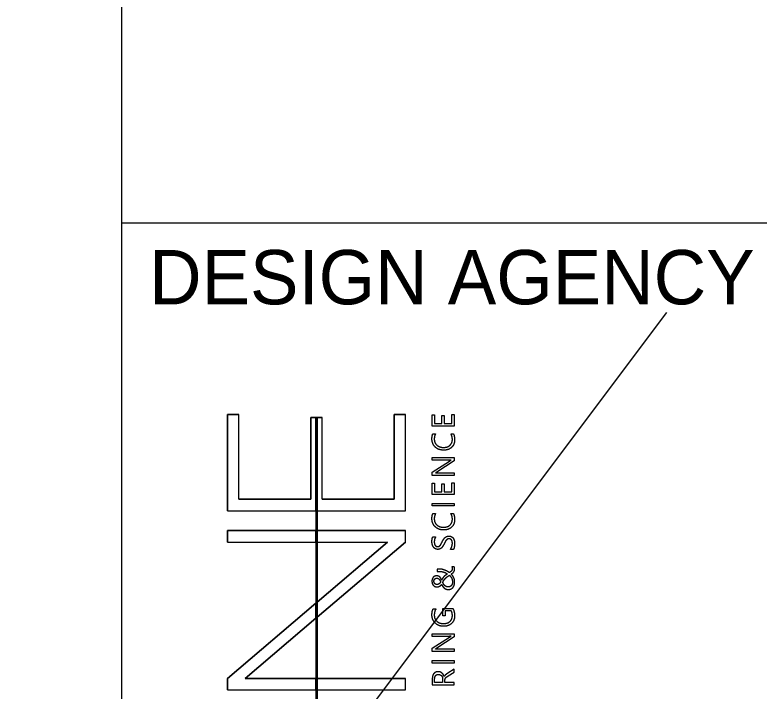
# Model space of a CAD drawing. Extents: x -5.2 to 34, y 0 to 22.
# Drawn here: x 31.803 to 33.173, y 3.638 to 4.883 of the extents above; entities that cross this region are included whole.
import ezdxf

# ---------------------------------------------------------------- set-up
doc = ezdxf.new("R2010")
doc.units = 0
for name, color, linetype in [('CS-ANNO', 7, 'Continuous'), ('CS-ANNO-MATC', 7, 'Continuous'), ('CS-ANNO-VFRM', 7, 'Continuous')]:
    doc.layers.add(name, color=color, linetype=linetype)

msp = doc.modelspace()

# ---------------------------------------------------------------- linework, layer by layer
at = {"layer": 'CS-ANNO'}
for p, q in [((32, 0.5), (32, 21.5)), ((32, 4.5), (33.5, 4.5))]:
    msp.add_line(p, q, dxfattribs=at)
at = {"layer": 'CS-ANNO-MATC'}
for p, q in [((32.1941, 4.1473), (32.2152, 4.1473)), ((32.1941, 3.9702), (32.1941, 4.1473)), ((32.2152, 3.9913), (32.2152, 4.1473)), ((32.3475, 3.9913), (32.3475, 4.1416)), ((32.3475, 4.1416), (32.3567, 4.1416)), ((32.3567, 4.1416), (32.3567, 3.5136)), ((32.3567, 4.1416), (32.3567, 3.9702)), ((32.3567, 4.1416), (32.3593, 4.1416)), ((32.3593, 4.1416), (32.3593, 3.5136)), ((32.3593, 4.1416), (32.3593, 3.9702)), ((32.3593, 4.1416), (32.3685, 4.1416)), ((32.3685, 3.9913), (32.3685, 4.1416)), ((32.5008, 4.1473), (32.5219, 4.1473)), ((32.5008, 3.9913), (32.5008, 4.1473)), ((32.5219, 3.9702), (32.5219, 4.1473)), ((32.5723, 4.1118), (32.5773, 4.1118)), ((32.6054, 4.1118), (32.61, 4.1118)), ((32.6057, 4.0632), (32.6057, 4.0634)), ((32.577, 4.0399), (32.577, 4.0397)), ((32.2152, 3.9913), (32.3475, 3.9913)), ((32.3685, 3.9913), (32.5008, 3.9913)), ((32.1941, 3.9702), (32.3567, 3.9702)), ((32.3593, 3.9702), (32.5219, 3.9702)), ((32.5723, 3.9649), (32.5773, 3.9649)), ((32.6054, 3.9649), (32.61, 3.9649)), ((32.1941, 3.9125), (32.1941, 3.9336)), ((32.1941, 3.9336), (32.3567, 3.9336)), ((32.3567, 3.9336), (32.3567, 3.9125)), ((32.3593, 3.9336), (32.3593, 3.9125)), ((32.3593, 3.9336), (32.5219, 3.9336)), ((32.5219, 3.9125), (32.5219, 3.9336)), ((32.5721, 3.9218), (32.5774, 3.9218)), ((32.1941, 3.9125), (32.3567, 3.9125)), ((32.3593, 3.802), (32.4891, 3.9125)), ((32.5219, 3.9125), (32.3593, 3.7742)), ((32.3593, 3.9125), (32.4891, 3.9125)), ((32.6101, 3.899), (32.6045, 3.899)), ((32.6116, 3.8669), (32.6073, 3.8669)), ((32.5801, 3.8624), (32.5801, 3.858)), ((32.6124, 3.8626), (32.6124, 3.8626)), ((32.5796, 3.846), (32.5796, 3.846)), ((32.6084, 3.839), (32.6084, 3.839)), ((32.1941, 3.6615), (32.3567, 3.7999)), ((32.3567, 3.7999), (32.3567, 3.7721)), ((32.3593, 3.802), (32.3593, 3.7742)), ((32.5728, 3.7895), (32.578, 3.7895)), ((32.3567, 3.7721), (32.2266, 3.6615)), ((32.6057, 3.7391), (32.6057, 3.7392)), ((32.577, 3.7157), (32.577, 3.7156)), ((32.1941, 3.6404), (32.1941, 3.6615)), ((32.2266, 3.6615), (32.3567, 3.6615)), ((32.3567, 3.6615), (32.3567, 3.6404)), ((32.3593, 3.6615), (32.3593, 3.6404)), ((32.3593, 3.6615), (32.5219, 3.6615)), ((32.5219, 3.6404), (32.5219, 3.6615)), ((32.5931, 3.6648), (32.593, 3.6648)), ((32.1941, 3.6404), (32.3567, 3.6404)), ((32.3593, 3.6404), (32.5219, 3.6404))]:
    msp.add_line(p, q, dxfattribs=at)
for points in [[(32.1941, 4.1473), (32.1941, 3.9702), (32.3567, 3.9702), (32.3567, 4.1416), (32.3475, 4.1416), (32.3475, 3.9913), (32.2152, 3.9913), (32.2152, 4.1473)], [(32.3685, 3.9913), (32.3685, 4.1416), (32.3593, 4.1416), (32.3593, 3.9702), (32.5219, 3.9702), (32.5219, 4.1473), (32.5008, 4.1473), (32.5008, 3.9913)], [(32.6117, 4.1473), (32.6117, 4.1258), (32.5713, 4.1258), (32.5713, 4.1464), (32.5756, 4.1464), (32.5756, 4.1306), (32.589, 4.1306), (32.589, 4.1452), (32.5933, 4.1452), (32.5933, 4.1306), (32.6075, 4.1306), (32.6075, 4.1473)], [(32.6117, 4.0216), (32.6117, 4.0002), (32.5713, 4.0002), (32.5713, 4.0207), (32.5756, 4.0207), (32.5756, 4.0049), (32.589, 4.0049), (32.589, 4.0195), (32.5933, 4.0195), (32.5933, 4.0049), (32.6075, 4.0049), (32.6075, 4.0216)], [(32.6117, 3.9837), (32.6117, 3.979), (32.5713, 3.979), (32.5713, 3.9837)], [(32.1941, 3.9336), (32.1941, 3.9125), (32.3567, 3.9125), (32.3567, 3.9336)], [(32.3593, 3.9336), (32.3593, 3.9125), (32.4891, 3.9125), (32.3593, 3.802), (32.3593, 3.7742), (32.5219, 3.9125), (32.5219, 3.9336)], [(32.1941, 3.6615), (32.1941, 3.6404), (32.3567, 3.6404), (32.3567, 3.6615), (32.2266, 3.6615), (32.3567, 3.7721), (32.3567, 3.7999)], [(32.6117, 3.6946), (32.6117, 3.6898), (32.5713, 3.6898), (32.5713, 3.6946)], [(32.3593, 3.6615), (32.3593, 3.6404), (32.5219, 3.6404), (32.5219, 3.6615)]]:
    msp.add_lwpolyline(points, close=True, dxfattribs=at)
for points in [[(32.4683, 3.51), (32.3618, 3.4836), (32.3618, 3.5136), (32.3593, 3.5136), (32.3593, 4.1416), (32.3567, 4.1416), (32.3567, 3.5136), (32.3542, 3.5136), (32.3542, 3.4817), (32.2948, 3.467)], [(32.5998, 4.0631), (32.5713, 4.0631), (32.5713, 4.0678), (32.6117, 4.0678), (32.6117, 4.062), (32.5795, 4.0412)], [(32.5825, 4.04), (32.6117, 4.04), (32.6117, 4.0352), (32.5713, 4.0352), (32.5713, 4.0414), (32.603, 4.0616)], [(32.6063, 3.7856), (32.5949, 3.7856), (32.5949, 3.7767), (32.5906, 3.7767), (32.5906, 3.7903), (32.609, 3.7903)], [(32.5998, 3.7389), (32.5713, 3.7389), (32.5713, 3.7436), (32.6117, 3.7436), (32.6117, 3.7378), (32.5795, 3.717)], [(32.5825, 3.7158), (32.6117, 3.7158), (32.6117, 3.711), (32.5713, 3.711), (32.5713, 3.7172), (32.603, 3.7374)], [(32.6004, 3.666), (32.6117, 3.6728), (32.6117, 3.6784), (32.5996, 3.6709)], [(32.5713, 3.6615), (32.5713, 3.6495), (32.6117, 3.6495), (32.6117, 3.6542), (32.5945, 3.6542), (32.5945, 3.6581)], [(32.5903, 3.6606), (32.5903, 3.6542), (32.5756, 3.6542), (32.5756, 3.6607)]]:
    msp.add_lwpolyline(points, dxfattribs=at)
for points in [[(32.5706, 4.1022), (32.5706, 4.108), (32.5723, 4.1118)], [(32.5773, 4.1118), (32.5749, 4.1074), (32.5749, 4.1022)], [(32.6082, 4.1012), (32.6082, 4.1073), (32.6054, 4.1118)], [(32.61, 4.1118), (32.6124, 4.1073), (32.6124, 4.1006)], [(32.5766, 4.0874), (32.5706, 4.0933), (32.5706, 4.1022)], [(32.5749, 4.1022), (32.5749, 4.0952), (32.5796, 4.0909)], [(32.6038, 4.0906), (32.6082, 4.0947), (32.6082, 4.1012)], [(32.6124, 4.1006), (32.6124, 4.092), (32.6069, 4.0868)], [(32.5923, 4.0816), (32.5826, 4.0816), (32.5766, 4.0874)], [(32.5796, 4.0909), (32.5842, 4.0866), (32.592, 4.0866)], [(32.592, 4.0866), (32.5994, 4.0866), (32.6038, 4.0906)], [(32.6069, 4.0868), (32.6013, 4.0816), (32.5923, 4.0816)], [(32.6057, 4.0634), (32.604, 4.0631), (32.5998, 4.0631)], [(32.603, 4.0616), (32.605, 4.0629), (32.6057, 4.0632)], [(32.5795, 4.0412), (32.5783, 4.0404), (32.577, 4.0399)], [(32.577, 4.0397), (32.5783, 4.04), (32.5825, 4.04)], [(32.5706, 3.9554), (32.5706, 3.9611), (32.5723, 3.9649)], [(32.5773, 3.9649), (32.5749, 3.9606), (32.5749, 3.9553)], [(32.6082, 3.9544), (32.6082, 3.9604), (32.6054, 3.9649)], [(32.61, 3.9649), (32.6124, 3.9604), (32.6124, 3.9537)], [(32.5766, 3.9406), (32.5706, 3.9464), (32.5706, 3.9554)], [(32.5749, 3.9553), (32.5749, 3.9484), (32.5796, 3.944)], [(32.6038, 3.9437), (32.6082, 3.9478), (32.6082, 3.9544)], [(32.6124, 3.9537), (32.6124, 3.9451), (32.6069, 3.9399)], [(32.5923, 3.9347), (32.5826, 3.9347), (32.5766, 3.9406)], [(32.5796, 3.944), (32.5842, 3.9397), (32.592, 3.9397)], [(32.592, 3.9397), (32.5994, 3.9397), (32.6038, 3.9437)], [(32.6069, 3.9399), (32.6013, 3.9347), (32.5923, 3.9347)], [(32.5706, 3.9131), (32.5706, 3.9191), (32.5721, 3.9218)], [(32.5774, 3.9218), (32.5749, 3.9182), (32.5749, 3.9126)], [(32.5917, 3.9169), (32.5929, 3.9188), (32.5943, 3.9203)], [(32.5943, 3.9203), (32.5958, 3.9218), (32.5975, 3.9226)], [(32.5975, 3.9226), (32.5993, 3.9235), (32.6015, 3.9235)], [(32.6019, 3.9185), (32.6002, 3.9185), (32.599, 3.9178)], [(32.6015, 3.9235), (32.6045, 3.9235), (32.6066, 3.9223)], [(32.6065, 3.9164), (32.6049, 3.9185), (32.6019, 3.9185)], [(32.6066, 3.9223), (32.6087, 3.9211), (32.61, 3.9192)], [(32.61, 3.9192), (32.6113, 3.9172), (32.6118, 3.9146)], [(32.5713, 3.9079), (32.5706, 3.9105), (32.5706, 3.9131)], [(32.5733, 3.9034), (32.5719, 3.9054), (32.5713, 3.9079)], [(32.5749, 3.9126), (32.5749, 3.9111), (32.5752, 3.9095)], [(32.5752, 3.9095), (32.5756, 3.9079), (32.5763, 3.9067)], [(32.5763, 3.9067), (32.577, 3.9055), (32.5782, 3.9048)], [(32.5782, 3.9048), (32.5793, 3.904), (32.581, 3.904)], [(32.581, 3.904), (32.5826, 3.904), (32.5837, 3.9046)], [(32.5837, 3.9046), (32.5848, 3.9052), (32.5857, 3.9063)], [(32.5857, 3.9063), (32.5867, 3.9074), (32.5875, 3.909)], [(32.5875, 3.909), (32.5884, 3.9107), (32.5895, 3.9128)], [(32.5908, 3.9051), (32.5897, 3.9033), (32.5884, 3.9019)], [(32.5895, 3.9128), (32.5905, 3.9149), (32.5917, 3.9169)], [(32.593, 3.9091), (32.5919, 3.907), (32.5908, 3.9051)], [(32.5949, 3.9128), (32.594, 3.9111), (32.593, 3.9091)], [(32.5968, 3.9158), (32.5958, 3.9145), (32.5949, 3.9128)], [(32.599, 3.9178), (32.5978, 3.9171), (32.5968, 3.9158)], [(32.6082, 3.9098), (32.6082, 3.9142), (32.6065, 3.9164)], [(32.6072, 3.9041), (32.6076, 3.9056), (32.6079, 3.9071)], [(32.6079, 3.9071), (32.6082, 3.9086), (32.6082, 3.9098)], [(32.6118, 3.9146), (32.6124, 3.912), (32.6124, 3.9091)], [(32.6123, 3.9067), (32.6121, 3.9053), (32.6118, 3.9039)], [(32.6124, 3.9091), (32.6124, 3.9081), (32.6123, 3.9067)], [(32.5766, 3.9003), (32.5746, 3.9015), (32.5733, 3.9034)], [(32.5814, 3.899), (32.5787, 3.899), (32.5766, 3.9003)], [(32.5854, 3.8998), (32.5837, 3.899), (32.5814, 3.899)], [(32.5884, 3.9019), (32.587, 3.9006), (32.5854, 3.8998)], [(32.6045, 3.899), (32.6054, 3.8999), (32.606, 3.9013)], [(32.606, 3.9013), (32.6067, 3.9026), (32.6072, 3.9041)], [(32.6111, 3.9011), (32.6106, 3.8998), (32.6101, 3.899)], [(32.6118, 3.9039), (32.6115, 3.9024), (32.6111, 3.9011)], [(32.6073, 3.8669), (32.6076, 3.866), (32.6079, 3.8651)], [(32.6081, 3.8634), (32.6081, 3.8623), (32.6078, 3.8614)], [(32.6079, 3.8651), (32.6081, 3.8642), (32.6081, 3.8634)], [(32.6122, 3.8648), (32.612, 3.8659), (32.6116, 3.8669)], [(32.6124, 3.8626), (32.6124, 3.8637), (32.6122, 3.8648)], [(32.5757, 3.8496), (32.5741, 3.8489), (32.573, 3.8476)], [(32.5792, 3.8503), (32.5773, 3.8503), (32.5757, 3.8496)], [(32.5848, 3.8484), (32.5826, 3.8503), (32.5792, 3.8503)], [(32.5819, 3.8627), (32.5811, 3.8627), (32.5801, 3.8624)], [(32.5801, 3.858), (32.5811, 3.8582), (32.582, 3.8583)], [(32.5839, 3.8628), (32.5827, 3.8628), (32.5819, 3.8627)], [(32.582, 3.8583), (32.583, 3.8584), (32.584, 3.8584)], [(32.589, 3.8623), (32.5864, 3.8628), (32.5839, 3.8628)], [(32.584, 3.8584), (32.5882, 3.8584), (32.5921, 3.8573)], [(32.5941, 3.8608), (32.5916, 3.8617), (32.589, 3.8623)], [(32.5921, 3.8573), (32.5959, 3.8561), (32.5991, 3.8538)], [(32.5959, 3.8516), (32.5943, 3.8504), (32.593, 3.8491)], [(32.5987, 3.8587), (32.5965, 3.8599), (32.5941, 3.8608)], [(32.5991, 3.8538), (32.5974, 3.8527), (32.5959, 3.8516)], [(32.5981, 3.8481), (32.6, 3.8495), (32.6027, 3.8513)], [(32.6027, 3.8562), (32.6009, 3.8575), (32.5987, 3.8587)], [(32.6051, 3.858), (32.6041, 3.8572), (32.6027, 3.8562)], [(32.6027, 3.8513), (32.6038, 3.8502), (32.6049, 3.849)], [(32.6068, 3.8597), (32.6061, 3.8588), (32.6051, 3.858)], [(32.6061, 3.8535), (32.6076, 3.8545), (32.6087, 3.8555)], [(32.6085, 3.8508), (32.6073, 3.8523), (32.6061, 3.8535)], [(32.6078, 3.8614), (32.6075, 3.8605), (32.6068, 3.8597)], [(32.6105, 3.8476), (32.6096, 3.8494), (32.6085, 3.8508)], [(32.6087, 3.8555), (32.6099, 3.8565), (32.6107, 3.8575)], [(32.6107, 3.8575), (32.6115, 3.8586), (32.6119, 3.8598)], [(32.6119, 3.8598), (32.6124, 3.861), (32.6124, 3.8626)], [(32.5712, 3.8444), (32.5706, 3.8426), (32.5706, 3.8404)], [(32.5706, 3.8404), (32.5706, 3.8382), (32.5712, 3.8363)], [(32.573, 3.8476), (32.5718, 3.8463), (32.5712, 3.8444)], [(32.5712, 3.8363), (32.5718, 3.8344), (32.573, 3.833)], [(32.5743, 3.8404), (32.5743, 3.8414), (32.5746, 3.8424)], [(32.5758, 3.836), (32.5743, 3.8377), (32.5743, 3.8404)], [(32.5746, 3.8424), (32.5749, 3.8434), (32.5756, 3.8442)], [(32.5756, 3.8442), (32.5762, 3.845), (32.5772, 3.8455)], [(32.5799, 3.8343), (32.5773, 3.8344), (32.5758, 3.836)], [(32.5772, 3.8455), (32.5782, 3.846), (32.5796, 3.846)], [(32.5796, 3.846), (32.5821, 3.846), (32.5838, 3.8443)], [(32.5838, 3.8443), (32.5854, 3.8425), (32.5866, 3.839)], [(32.5855, 3.8372), (32.5848, 3.8363), (32.5839, 3.8357)], [(32.5886, 3.8426), (32.5871, 3.8465), (32.5848, 3.8484)], [(32.5866, 3.839), (32.5862, 3.838), (32.5855, 3.8372)], [(32.5905, 3.8461), (32.5894, 3.8446), (32.5886, 3.8426)], [(32.593, 3.8491), (32.5916, 3.8477), (32.5905, 3.8461)], [(32.5906, 3.8381), (32.5915, 3.8403), (32.5925, 3.842)], [(32.5922, 3.8348), (32.5914, 3.8363), (32.5906, 3.8381)], [(32.5925, 3.842), (32.5935, 3.8437), (32.5948, 3.8451)], [(32.5948, 3.8451), (32.5962, 3.8466), (32.5981, 3.8481)], [(32.6049, 3.849), (32.6059, 3.8478), (32.6067, 3.8462)], [(32.6067, 3.8462), (32.6075, 3.8447), (32.6079, 3.8429)], [(32.6079, 3.8429), (32.6084, 3.8411), (32.6084, 3.839)], [(32.6084, 3.839), (32.6084, 3.8371), (32.6079, 3.8354)], [(32.6119, 3.8436), (32.6113, 3.8458), (32.6105, 3.8476)], [(32.6116, 3.8334), (32.6124, 3.8359), (32.6124, 3.839)], [(32.6124, 3.839), (32.6124, 3.8415), (32.6119, 3.8436)], [(32.573, 3.833), (32.5742, 3.8315), (32.5759, 3.8307)], [(32.5759, 3.8307), (32.5777, 3.8299), (32.5799, 3.8299)], [(32.582, 3.8347), (32.581, 3.8343), (32.5799, 3.8343)], [(32.5799, 3.8299), (32.5814, 3.8299), (32.5827, 3.8303)], [(32.5839, 3.8357), (32.5831, 3.835), (32.582, 3.8347)], [(32.5827, 3.8303), (32.584, 3.8308), (32.585, 3.8314)], [(32.585, 3.8314), (32.5861, 3.8321), (32.5869, 3.8329)], [(32.5869, 3.8329), (32.5877, 3.8338), (32.5884, 3.8346)], [(32.5884, 3.8346), (32.5903, 3.8301), (32.5934, 3.8277)], [(32.5942, 3.8323), (32.5931, 3.8333), (32.5922, 3.8348)], [(32.5934, 3.8277), (32.5964, 3.8252), (32.6007, 3.8252)], [(32.597, 3.8306), (32.5954, 3.8312), (32.5942, 3.8323)], [(32.6006, 3.8299), (32.5985, 3.8299), (32.597, 3.8306)], [(32.604, 3.8306), (32.6025, 3.8299), (32.6006, 3.8299)], [(32.6007, 3.8252), (32.6036, 3.8252), (32.6057, 3.8262)], [(32.6064, 3.8326), (32.6054, 3.8313), (32.604, 3.8306)], [(32.6057, 3.8262), (32.6079, 3.8272), (32.6094, 3.829)], [(32.6079, 3.8354), (32.6074, 3.8338), (32.6064, 3.8326)], [(32.6094, 3.829), (32.6109, 3.8308), (32.6116, 3.8334)], [(32.5706, 3.7784), (32.5706, 3.785), (32.5728, 3.7895)], [(32.578, 3.7895), (32.5749, 3.7846), (32.5749, 3.7779)], [(32.6082, 3.7774), (32.6082, 3.7821), (32.6063, 3.7856)], [(32.609, 3.7903), (32.6124, 3.7842), (32.6124, 3.7768)], [(32.5766, 3.7634), (32.5706, 3.7693), (32.5706, 3.7784)], [(32.5749, 3.7779), (32.5749, 3.7711), (32.5796, 3.7667)], [(32.6038, 3.7664), (32.6082, 3.7705), (32.6082, 3.7774)], [(32.6124, 3.7768), (32.6124, 3.7681), (32.6068, 3.7628)], [(32.5921, 3.7574), (32.5827, 3.7574), (32.5766, 3.7634)], [(32.5796, 3.7667), (32.5843, 3.7624), (32.5917, 3.7624)], [(32.5917, 3.7624), (32.5994, 3.7624), (32.6038, 3.7664)], [(32.6068, 3.7628), (32.6012, 3.7574), (32.5921, 3.7574)], [(32.6057, 3.7392), (32.604, 3.7389), (32.5998, 3.7389)], [(32.603, 3.7374), (32.605, 3.7387), (32.6057, 3.7391)], [(32.5795, 3.717), (32.5783, 3.7162), (32.577, 3.7157)], [(32.577, 3.7156), (32.5783, 3.7158), (32.5825, 3.7158)], [(32.5774, 3.6729), (32.5753, 3.672), (32.574, 3.6703)], [(32.5821, 3.6738), (32.5794, 3.6738), (32.5774, 3.6729)], [(32.586, 3.6732), (32.5842, 3.6738), (32.5821, 3.6738)], [(32.5891, 3.6714), (32.5877, 3.6725), (32.586, 3.6732)], [(32.572, 3.6664), (32.5713, 3.6642), (32.5713, 3.6615)], [(32.574, 3.6703), (32.5726, 3.6687), (32.572, 3.6664)], [(32.5756, 3.6607), (32.5756, 3.6646), (32.5774, 3.6667)], [(32.5774, 3.6667), (32.5792, 3.6688), (32.5825, 3.6688)], [(32.5825, 3.6688), (32.5843, 3.6688), (32.5857, 3.6682)], [(32.5857, 3.6682), (32.5872, 3.6676), (32.5882, 3.6665)], [(32.5882, 3.6665), (32.5892, 3.6654), (32.5897, 3.6639)], [(32.5915, 3.6686), (32.5905, 3.6702), (32.5891, 3.6714)], [(32.5897, 3.6639), (32.5903, 3.6624), (32.5903, 3.6606)], [(32.593, 3.6648), (32.5924, 3.6669), (32.5915, 3.6686)], [(32.5941, 3.6666), (32.5935, 3.6659), (32.5931, 3.6648)], [(32.5955, 3.668), (32.5947, 3.6674), (32.5941, 3.6666)], [(32.5945, 3.6581), (32.5945, 3.6594), (32.5949, 3.6605)], [(32.5949, 3.6605), (32.5952, 3.6615), (32.5959, 3.6624)], [(32.5973, 3.6694), (32.5963, 3.6687), (32.5955, 3.668)], [(32.5959, 3.6624), (32.5966, 3.6634), (32.5977, 3.6642)], [(32.5996, 3.6709), (32.5983, 3.67), (32.5973, 3.6694)], [(32.5977, 3.6642), (32.5988, 3.6651), (32.6004, 3.666)]]:
    msp.add_open_spline(points, degree=2, dxfattribs=at)
at = {"layer": 'CS-ANNO-VFRM'}
msp.add_line((31.8029, 2.7351), (33.0029, 4.3351), dxfattribs=at)

# ---------------------------------------------------------------- texts
at = {"layer": 'CS-ANNO-MATC'}
msp.add_text('DESIGN AGENCY', height=0.1, dxfattribs=at).set_placement((32.05, 4.35))

doc.saveas('drawing.dxf')
